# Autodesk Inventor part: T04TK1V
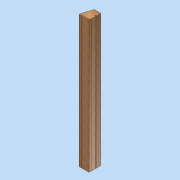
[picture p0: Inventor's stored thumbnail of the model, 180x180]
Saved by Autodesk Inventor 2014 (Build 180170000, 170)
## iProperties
Created: 2012-03
Part Number: T04TK1V
Document SubType Name: Modeling
Designer: david.appleford
Density: 0.44 g/cm^3
Description: 1w Threshold Timber Assy
Mass: 3536.13 g
Surface Area: 4276.67 cm^2
Volume: 8036.66 cm^3
Cost Center: £30.00
Material: 000 Redwood
Appearance: Wood (Oak)
Justset: False
Author: david.appleford
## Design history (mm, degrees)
sketch "Sketch1"
  geometry: L1 (-72.469, 53.035)-(-84, 10) reference; L2 (-84, 0)-(-84, 10) reference; L3 (-84, 0)-(0, 0) reference; L4 (0, 0)-(0, 56) reference; L5 (0, 56)-(-68.605, 56) reference; L6 (-68, 56)-(-57.005, 97.035) reference; L7 (-10, 56)-(-68, 56) reference; L8 (-10, 61)-(-10, 56) reference; L9 (0, 61)-(-10, 61) reference; L10 (0, 100)-(0, 61) reference; L11 (-53.141, 100)-(0, 100) reference; A1 r 4 centre (-68.605, 52) between (-68.605, 56) and (-72.469, 53.035) reference; A2 r 4 centre (-53.141, 96) between (-53.141, 100) and (-57.005, 97.035) reference
  node "Reference1"
  node "Reference2"
workplane "Work Plane1"
extrude "Extrusion1" new body sketch "Sketch1" stored distance "d0" = 10; taper "d1" = 0 deg
body "Solid1"
